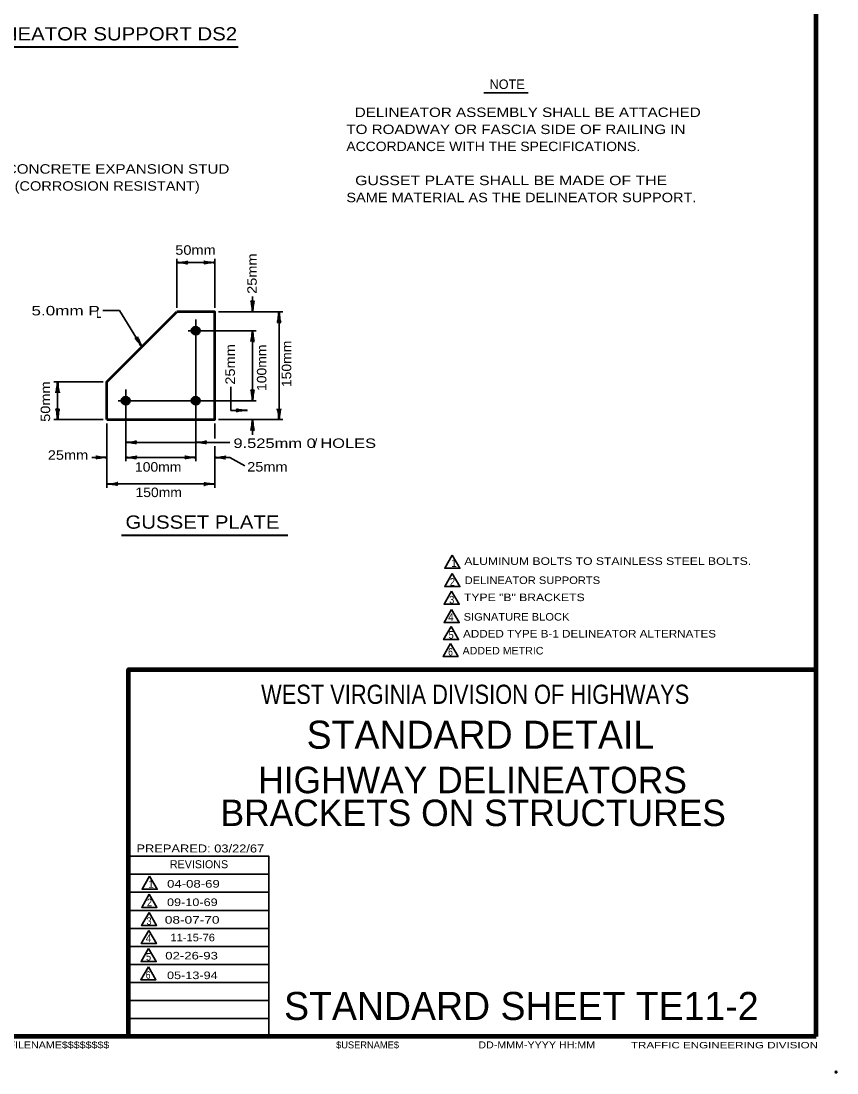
# Model space of a CAD drawing. Extents: x -105 to 751, y -65 to 479.
# Drawn here: x 492 to 750.7, y -65 to 268.5 of the extents above; entities that cross this region are included whole.
import ezdxf
from ezdxf.enums import TextEntityAlignment as Align

# ---------------------------------------------------------------- set-up
doc = ezdxf.new("R2010")
doc.units = 0
doc.header["$LTSCALE"] = 1.2
doc.header["$PDMODE"] = 32
doc.header["$PDSIZE"] = 0.6
doc.layers.add('1', color=7, linetype='Continuous', lineweight=35)
doc.layers.add('61', color=7, linetype='Continuous', lineweight=35)

msp = doc.modelspace()

# ---------------------------------------------------------------- hatches: boundary and pattern name
at = {"layer": '1'}
for points in [[(548.637, 170.312, 1), (546.237, 170.312, 1)], [(526.437, 148.112, 1), (524.037, 148.112, 1)], [(548.637, 148.112, 1), (546.237, 148.112, 1)]]:
    msp.add_hatch(color=256, dxfattribs=at).paths.add_polyline_path(points)

# ---------------------------------------------------------------- linework, layer by layer
at = {"layer": '1', "lineweight": 158}
for q in [(744.128, 472.7), (744.128, 62.9), (-47.472, -53.4)]:
    msp.add_line((744.128, -53.4), q, dxfattribs=at)
at = {"layer": '1', "lineweight": 13}
msp.add_line((744.128, -53.4), (744.128, 472.7), dxfattribs=at)
at = {"layer": '1', "lineweight": 40}
for p, q in [((470.651, 260.331), (560.871, 260.331)), ((523.903, 105.542), (576.605, 105.542))]:
    msp.add_line(p, q, dxfattribs=at)
at = {"layer": '1'}
for p, q in [((638.817, 245.768), (652.824, 245.768)), ((541.437, 177.512), (541.437, 193.112)), ((541.437, 191.912), (553.437, 191.912)), ((553.437, 177.512), (553.437, 193.112)), ((565.437, 176.312), (565.437, 181.112)), ((547.437, 128.912), (547.437, 173.912)), ((554.637, 176.312), (575.037, 176.312)), ((573.837, 176.312), (573.837, 142.112)), ((566.637, 170.312), (545.037, 170.312)), ((565.437, 170.312), (565.437, 148.112)), ((518.037, 154.112), (502.437, 154.112)), ((503.637, 154.112), (503.637, 142.112)), ((525.237, 128.912), (525.237, 151.712)), ((522.837, 148.112), (566.637, 148.112)), ((518.037, 142.112), (502.437, 142.112)), ((519.237, 140.912), (519.237, 120.512)), ((553.437, 140.912), (553.437, 136.112)), ((554.637, 142.112), (575.037, 142.112)), ((565.437, 142.112), (565.437, 137.312)), ((553.437, 133.712), (553.437, 120.512)), ((519.237, 130.112), (514.437, 130.112)), ((525.237, 130.112), (547.437, 130.112)), ((553.437, 130.112), (558.237, 130.112)), ((558.237, 130.112), (563.022, 127.46)), ((519.237, 121.712), (553.437, 121.712)), ((570.628, -2), (526.128, -2)), ((570.628, -7.7), (526.128, -7.7)), ((570.628, -13.5), (526.128, -13.5)), ((570.628, -19.2), (526.128, -19.2)), ((570.628, -24.9), (526.128, -24.9)), ((570.628, -30.6), (526.128, -30.6)), ((570.628, -36.3), (526.128, -36.3)), ((570.628, -42), (526.128, -42)), ((570.628, -47.7), (526.128, -47.7))]:
    msp.add_line(p, q, dxfattribs=at)
for points in [[(530.337, 165.212), (523.226, 176.706), (517.967, 176.706)], [(558.583, 152.502), (558.583, 145.042), (563.732, 145.042)], [(525.237, 134.912), (547.437, 134.912), (558.237, 134.912)], [(570.628, -53.4), (570.628, 3.7), (526.128, 3.7)]]:
    msp.add_lwpolyline(points, dxfattribs=at)
at = {"layer": '1', "lineweight": 53}
for points in [[(519.237, 142.112), (553.437, 142.112), (553.437, 176.312), (541.437, 176.312)], [(519.237, 142.112), (519.237, 154.112), (541.437, 176.312)]]:
    msp.add_lwpolyline(points, dxfattribs=at)
at = {"layer": '1'}
for points in [[(628.759, 99.14), (626.359, 94.983), (631.159, 94.983)], [(628.759, 93.335), (626.359, 89.178), (631.159, 89.178)], [(628.559, 87.73), (626.159, 83.573), (630.959, 83.573)], [(628.559, 81.925), (626.159, 77.768), (630.959, 77.768)], [(628.386, 76.551), (625.986, 72.394), (630.786, 72.394)], [(628.228, 71.187), (625.828, 67.03), (630.628, 67.03)], [(532.806, -2.615), (530.406, -6.772), (535.206, -6.772)], [(532.692, -8.37), (530.292, -12.527), (535.092, -12.527)], [(532.614, -14.089), (530.214, -18.246), (535.014, -18.246)], [(532.571, -19.808), (530.171, -23.965), (534.971, -23.965)], [(532.485, -25.553), (530.085, -29.71), (534.885, -29.71)], [(532.406, -31.309), (530.006, -35.466), (534.806, -35.466)]]:
    msp.add_lwpolyline(points, close=True, dxfattribs=at)
at = {"layer": '1', "lineweight": 158}
msp.add_lwpolyline([(526.128, -53.4), (526.128, 62.9), (744.128, 62.9)], dxfattribs=at)
at = {"layer": '1', "lineweight": 53}
for centre in [(547.437, 170.312), (525.237, 148.112), (547.437, 148.112)]:
    msp.add_circle(centre, 1.2, dxfattribs=at)
at = {"layer": '1', "lineweight": 40}
for centre, major_axis, ratio, start_param, end_param in [((542.746, 192.244), (-2.143, -0.187), 0.122415, 0.8963533, 3.1415927), ((542.782, 191.658), (-2.108, 0.211), 0.07063, 3.1407148, 5.41811), ((552.128, 191.581), (2.143, 0.187), 0.122415, 0.8963533, 3.1415927), ((552.092, 192.166), (2.108, -0.211), 0.07063, 3.1407148, 5.41811), ((565.105, 177.622), (0.187, -2.143), 0.122415, 0.8963533, 3.1415927), ((565.691, 177.657), (-0.211, -2.108), 0.07063, 3.1407148, 5.41811), ((573.583, 174.968), (0.211, 2.108), 0.07063, 3.1407148, 5.41811), ((573.583, 174.968), (0.211, 2.108), 0.07063, 3.1407148, 5.41811), ((574.169, 175.003), (-0.187, 2.143), 0.122415, 0.8963533, 3.1415927), ((574.169, 175.003), (-0.187, 2.143), 0.122415, 0.8963533, 3.1415927), ((565.183, 168.968), (0.211, 2.108), 0.07063, 3.1407148, 5.41811), ((565.183, 168.968), (0.211, 2.108), 0.07063, 3.1407148, 5.41811), ((565.769, 169.003), (-0.187, 2.143), 0.122415, 0.8963533, 3.1415927), ((565.769, 169.003), (-0.187, 2.143), 0.122415, 0.8963533, 3.1415927), ((529.366, 166.151), (1.287, -1.724), 0.122415, 0.8963533, 3.1415927), ((529.366, 166.151), (1.287, -1.724), 0.122415, 0.8963533, 3.1415927), ((529.845, 166.489), (0.93, -1.903), 0.07063, 3.1407148, 5.41811), ((529.845, 166.489), (0.93, -1.903), 0.07063, 3.1407148, 5.41811), ((503.383, 152.768), (0.211, 2.108), 0.07063, 3.1407148, 5.41811), ((503.383, 152.768), (0.211, 2.108), 0.07063, 3.1407148, 5.41811), ((503.969, 152.803), (-0.187, 2.143), 0.122415, 0.8963533, 3.1415927), ((503.969, 152.803), (-0.187, 2.143), 0.122415, 0.8963533, 3.1415927), ((565.105, 149.422), (0.187, -2.143), 0.122415, 0.8963533, 3.1415927), ((565.105, 149.422), (0.187, -2.143), 0.122415, 0.8963533, 3.1415927), ((565.691, 149.457), (-0.211, -2.108), 0.07063, 3.1407148, 5.41811), ((565.691, 149.457), (-0.211, -2.108), 0.07063, 3.1407148, 5.41811), ((503.305, 143.422), (0.187, -2.143), 0.122415, 0.8963533, 3.1415927), ((503.891, 143.457), (-0.211, -2.108), 0.07063, 3.1407148, 5.41811), ((562.422, 144.711), (2.143, 0.187), 0.122415, 0.8963533, 3.1415927), ((562.387, 145.296), (2.108, -0.211), 0.07063, 3.1407148, 5.41811), ((573.505, 143.422), (0.187, -2.143), 0.122415, 0.8963533, 3.1415927), ((573.505, 143.422), (0.187, -2.143), 0.122415, 0.8963533, 3.1415927), ((574.091, 143.457), (-0.211, -2.108), 0.07063, 3.1407148, 5.41811), ((574.091, 143.457), (-0.211, -2.108), 0.07063, 3.1407148, 5.41811), ((565.183, 140.768), (0.211, 2.108), 0.07063, 3.1407148, 5.41811), ((565.769, 140.803), (-0.187, 2.143), 0.122415, 0.8963533, 3.1415927), ((526.546, 135.244), (-2.143, -0.187), 0.122415, 0.8963533, 3.1415927), ((526.546, 135.244), (-2.143, -0.187), 0.122415, 0.8963533, 3.1415927), ((526.582, 134.658), (-2.108, 0.211), 0.07063, 3.1407148, 5.41811), ((526.582, 134.658), (-2.108, 0.211), 0.07063, 3.1407148, 5.41811), ((548.746, 135.244), (-2.143, -0.187), 0.122415, 0.8963533, 3.1415927), ((548.746, 135.244), (-2.143, -0.187), 0.122415, 0.8963533, 3.1415927), ((548.782, 134.658), (-2.108, 0.211), 0.07063, 3.1407148, 5.41811), ((548.782, 134.658), (-2.108, 0.211), 0.07063, 3.1407148, 5.41811), ((517.928, 129.781), (2.143, 0.187), 0.122415, 0.8963533, 3.1415927), ((517.928, 129.781), (2.143, 0.187), 0.122415, 0.8963533, 3.1415927), ((517.892, 130.366), (2.108, -0.211), 0.07063, 3.1407148, 5.41811), ((517.892, 130.366), (2.108, -0.211), 0.07063, 3.1407148, 5.41811), ((526.546, 130.444), (-2.143, -0.187), 0.122415, 0.8963533, 3.1415927), ((526.546, 130.444), (-2.143, -0.187), 0.122415, 0.8963533, 3.1415927), ((526.582, 129.858), (-2.108, 0.211), 0.07063, 3.1407148, 5.41811), ((526.582, 129.858), (-2.108, 0.211), 0.07063, 3.1407148, 5.41811), ((546.128, 129.781), (2.143, 0.187), 0.122415, 0.8963533, 3.1415927), ((546.128, 129.781), (2.143, 0.187), 0.122415, 0.8963533, 3.1415927), ((546.092, 130.366), (2.108, -0.211), 0.07063, 3.1407148, 5.41811), ((546.092, 130.366), (2.108, -0.211), 0.07063, 3.1407148, 5.41811), ((554.746, 130.444), (-2.143, -0.187), 0.122415, 0.8963533, 3.1415927), ((554.782, 129.858), (-2.108, 0.211), 0.07063, 3.1407148, 5.41811), ((520.546, 122.044), (-2.143, -0.187), 0.122415, 0.8963533, 3.1415927), ((520.546, 122.044), (-2.143, -0.187), 0.122415, 0.8963533, 3.1415927), ((520.582, 121.458), (-2.108, 0.211), 0.07063, 3.1407148, 5.41811), ((520.582, 121.458), (-2.108, 0.211), 0.07063, 3.1407148, 5.41811), ((552.128, 121.381), (2.143, 0.187), 0.122415, 0.8963533, 3.1415927), ((552.128, 121.381), (2.143, 0.187), 0.122415, 0.8963533, 3.1415927), ((552.092, 121.966), (2.108, -0.211), 0.07063, 3.1407148, 5.41811), ((552.092, 121.966), (2.108, -0.211), 0.07063, 3.1407148, 5.41811)]:
    msp.add_ellipse(centre, major_axis=major_axis, ratio=ratio, start_param=start_param, end_param=end_param, dxfattribs=at)
at = {"layer": '1'}
msp.add_point((750.428, -64.7), dxfattribs=at)
at = {"layer": '61', "lineweight": 53}
for q in [(591.428, -53.4), (591.428, -53.4), (591.428, -53.4), (591.728, -53.4), (591.728, -53.4)]:
    msp.add_line((744.128, -53.4), q, dxfattribs=at)

# ---------------------------------------------------------------- texts
at = {"layer": '1'}
for s, height, width, p in [('DELINEATOR SUPPORT DS2', 4.2, 1.15, (471.899, 262.327)), ('  DELINEATOR ASSEMBLY SHALL BE ATTACHED', 3, 1.2, (595.178, 238.048)), ('TO ROADWAY OR FASCIA SIDE OF RAILING IN', 3, 1.2, (595.178, 232.648)), ('ACCORDANCE WITH THE SPECIFICATIONS.', 3, 1.1, (595.178, 227.248)), ('  GUSSET PLATE SHALL BE MADE OF THE', 3, 1.25, (595.178, 216.448)), ('SAME MATERIAL AS THE DELINEATOR SUPPORT.', 3, 1.15, (595.178, 211.048)), ('50mm', 3, 1.15, (540.935, 194.389)), ('5.0mm P', 3, 1.35, (495.343, 175.164)), ('L', 3, 0.75, (515.828, 174.377)), ('9.525mm 0 HOLES', 3, 1.3, (559.383, 133.139)), ('25mm', 3, 1.15, (500.519, 129.397)), ('100mm', 3, 1.1, (528.157, 125.628)), ('25mm', 3, 1.15, (563.729, 125.667)), ('150mm', 3, 1.1, (528.323, 117.568)), ('GUSSET PLATE', 4.2, 1.15, (525.151, 107.539)), ('ALUMINUM BOLTS TO STAINLESS STEEL BOLTS.', 2.4, 1.2, (632.575, 96.063)), ('2', 2.4, 0.9, (628.003, 89.469)), ('DELINEATOR SUPPORTS', 2.4, 1.1, (632.682, 90.001)), ('TYPE "B" BRACKETS', 2.4, 1.2, (632.469, 84.576)), ('3', 2.4, 0.9, (627.791, 83.832)), ('4', 2.4, 0.95, (627.472, 78.301)), ('SIGNATURE BLOCK', 2.4, 1.1, (632.363, 78.407)), ('5', 2.4, 0.9, (627.603, 72.678)), ('ADDED TYPE B-1 DELINEATOR ALTERNATES', 2.4, 1.15, (632.19, 73.034)), ('ADDED METRIC', 2.4, 1.05, (632.032, 67.67)), ('6', 2.4, 0.85, (627.445, 67.314)), ('PREPARED: 03/22/67', 2.537, 1.2, (528.628, 4.9)), ('2', 2.4, 0.9, (531.953, -12.134)), ('3', 2.4, 0.9, (531.821, -18.052)), ('4', 2.4, 0.95, (531.605, -23.49)), ('5', 2.4, 0.9, (531.661, -29.377)), ('6', 2.4, 0.85, (531.582, -35.133)), ('$$$$$$$$$FILENAME$$$$$$$$', 2.2, 1.15, (471.128, -57.2)), ('DD-MMM-YYYY HH:MM', 2.2, 1.15, (637.028, -57.2)), ('TRAFFIC ENGINEERING DIVISION', 2.031, 1.35, (685.428, -57.2))]:
    msp.add_text(s, height=height, dxfattribs=dict(at, width=width)).set_placement(p)
for s, height, p in [('NOTE', 3, (640.587, 246.947)), ('/', 3, (584.841, 133.126)), ('1', 2.4, (628.429, 95.425)), ('REVISIONS', 2.537, (539.228, -0.1)), ('1', 2.4, (532.374, -6.3)), ('STANDARD SHEET TE11-2', 8.881, (575.428, -48.2)), ('$USERNAME$', 2.2, (591.928, -57.2))]:
    msp.add_text(s, height=height, dxfattribs=at).set_placement(p)
for s, height, width, p in [('9.525mmx54.0mm CONCRETE EXPANSION STUD', 3, 1.2, (502.049, 220.089)), ('ANCHOR BOLT (CORROSION RESISTANT)', 3, 1.15, (502.049, 214.689)), ('WEST VIRGINIA DIVISION OF HIGHWAYS', 6.089, 0.85, (636.028, 52)), ('04-08-69', 2.4, 1.3, (546.691, -6.244)), ('09-10-69', 2.4, 1.25, (546.353, -12.074)), ('08-07-70', 2.4, 1.35, (546.298, -17.669)), ('11-15-76', 2.4, 1.1, (546.455, -23.263)), ('02-26-93', 2.4, 1.3, (546.106, -29.019)), ('05-13-94', 2.4, 1.25, (546.353, -35.249))]:
    msp.add_text(s, height=height, dxfattribs=dict(at, width=width)).set_placement(p, align=Align.CENTER)
for s, width, p in [('25mm', 1.15, (566.767, 181.983)), ('150mm', 1.1, (577.706, 152.428)), ('25mm', 1.15, (559.842, 153.211)), ('100mm', 1.1, (569.825, 151.197)), ('50mm', 1.15, (501.259, 141.422))]:
    msp.add_text(s, height=3, rotation=90, dxfattribs=dict(at, width=width)).set_placement(p)
for s, height, p in [('STANDARD DETAIL', 8.881, (637.678, 37.8)), ('HIGHWAY DELINEATORS', 8.391, (635.194, 23.684)), ('BRACKETS ON STRUCTURES', 8.391, (635.394, 13.275))]:
    msp.add_text(s, height=height, dxfattribs=at).set_placement(p, align=Align.CENTER)

doc.saveas('drawing.dxf')
